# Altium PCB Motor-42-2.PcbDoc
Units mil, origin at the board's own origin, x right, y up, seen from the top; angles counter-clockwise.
Board outline 3535 x 3245 mil, 2 copper layers (Top Layer, Bottom Layer); 0 components, 0 nets, 0 pads, 0 vias.
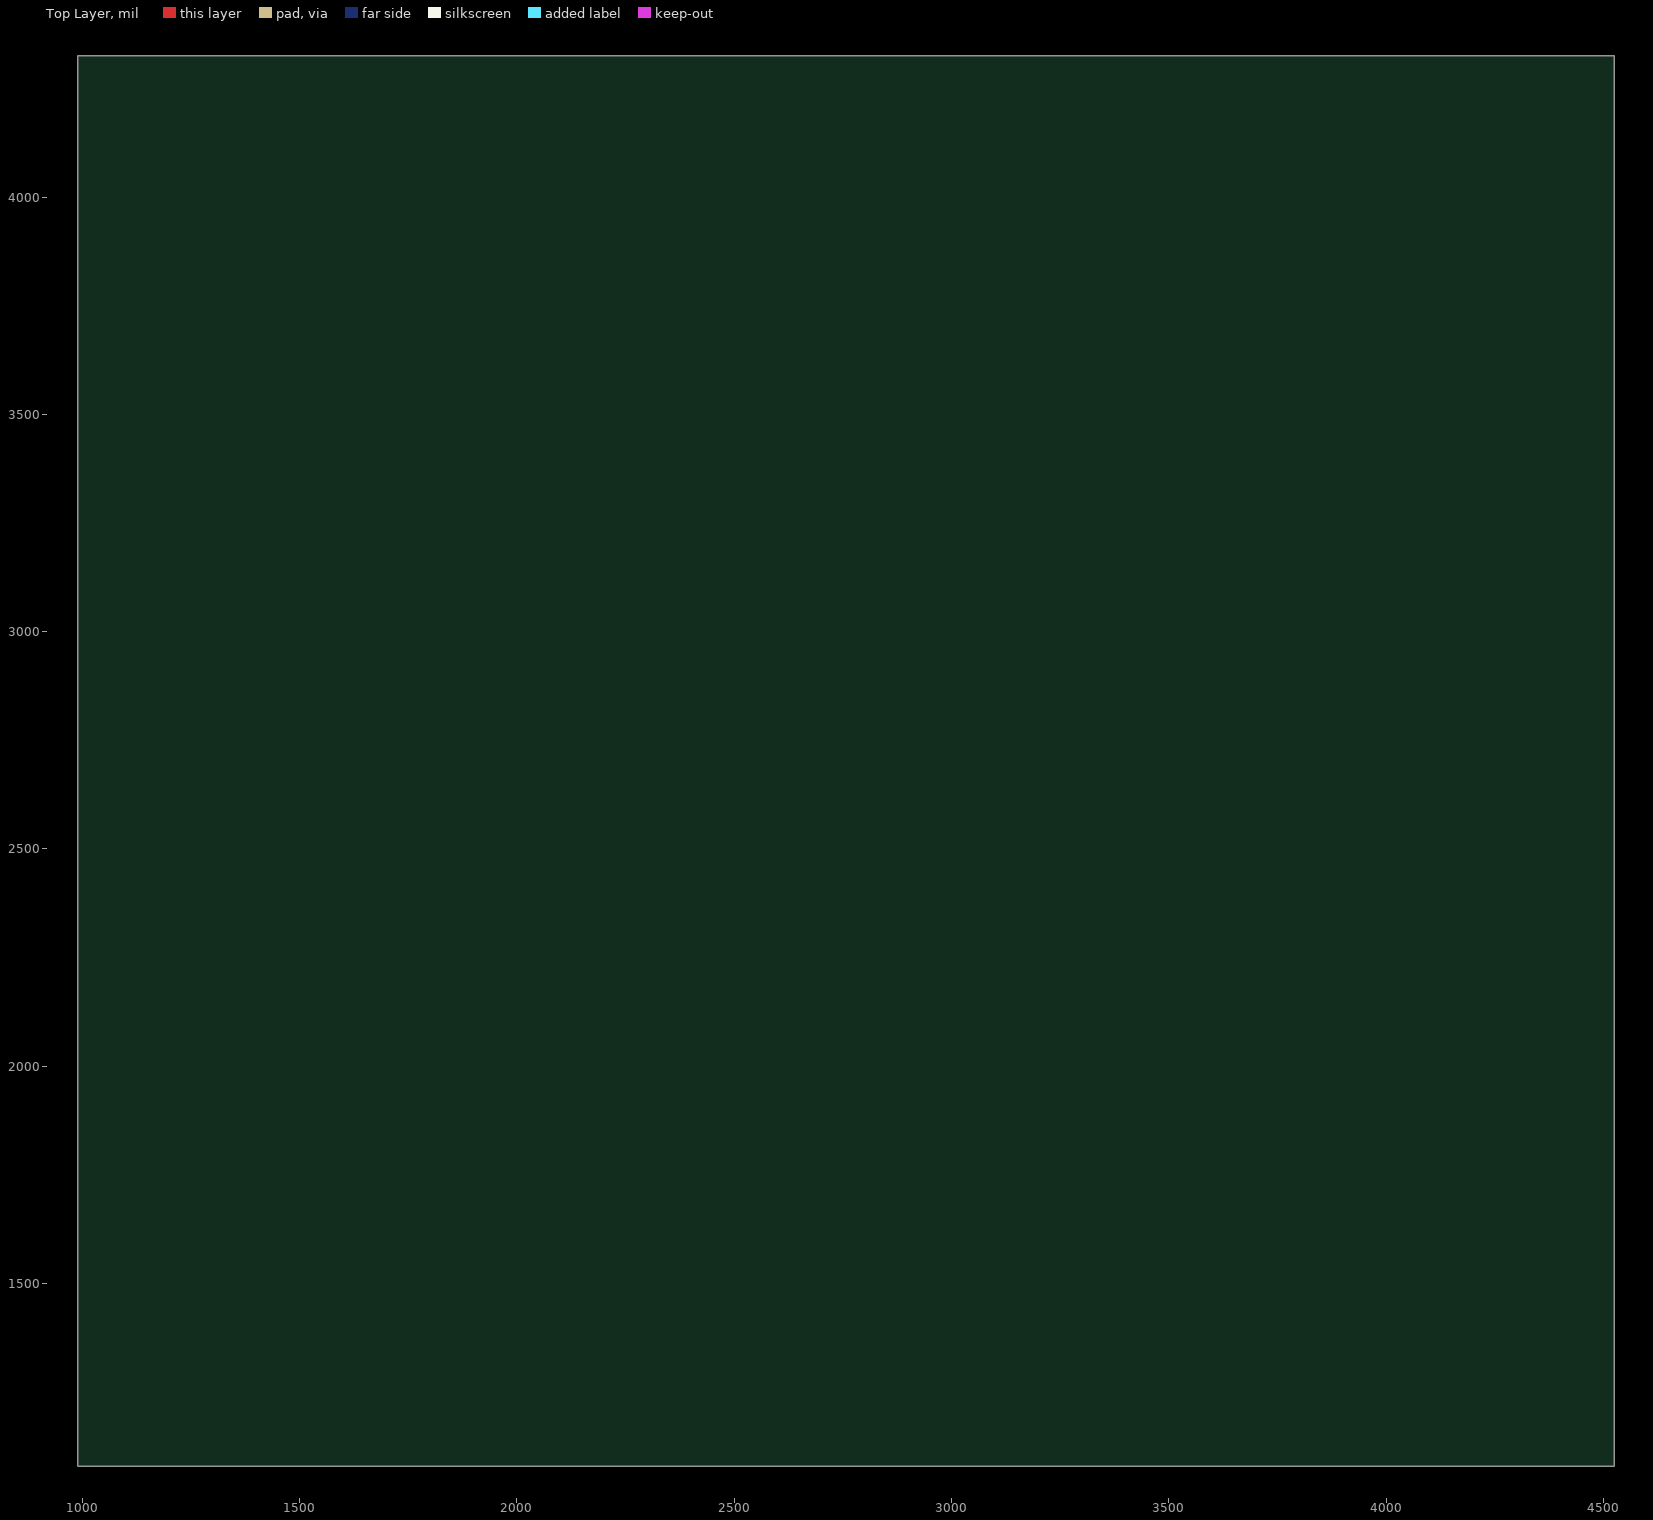
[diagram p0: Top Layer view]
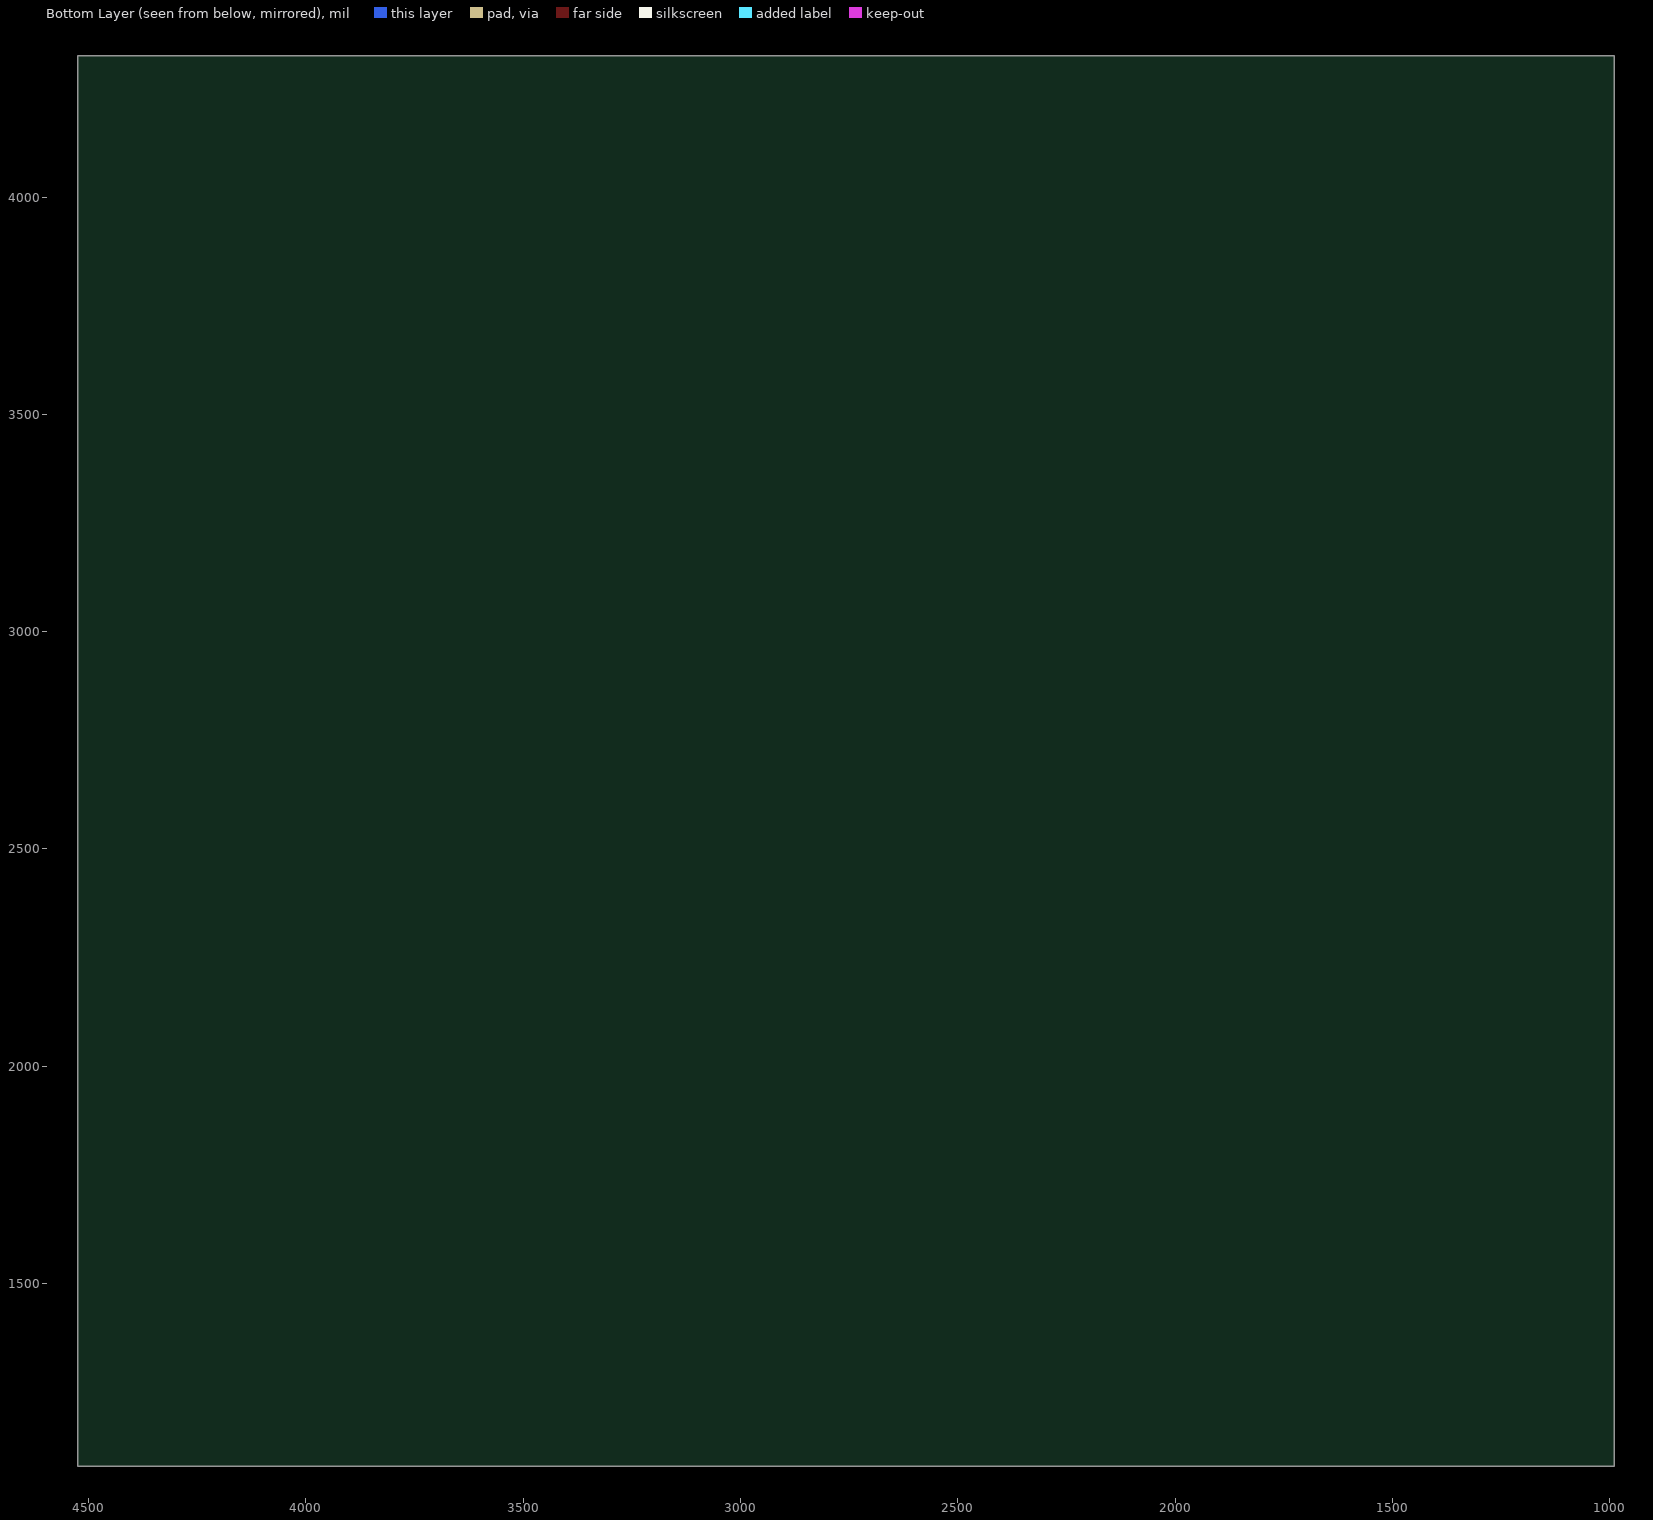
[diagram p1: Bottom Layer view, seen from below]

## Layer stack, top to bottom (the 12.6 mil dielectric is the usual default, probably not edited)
Top Solder: solder mask 0.4, Solder Resist, Dk 3.5
Top Layer: signal copper 1.4
Dielectric 1: dielectric 12.6, FR-4, Dk 4.8
Bottom Layer: signal copper 1.4
Bottom Solder: solder mask 0.4, Solder Resist, Dk 3.5

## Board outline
990,1080 4525,1080 4525,4325 990,4325

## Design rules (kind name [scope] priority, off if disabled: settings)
Clearance [All] p1: gap=10 ignorepadtopadclearanceinfootprint=FALSE except(0: Arc-Hole Track-Hole SMDPad-Hole THPad-Hole Via-Hole Fill-Hole Poly-Hole Region-Hole Text-Hole)
PolygonConnect [All] p1: connectstyle=Relief reliefconductorwidth=10 reliefentries=4 polygonreliefangle="90 Angle" airgapwidth=10
RoutingVias [All] p1: holewidth=28 width=50 viastyle="Through Hole" minholewidth=28 minwidth=50 maxholewidth=28 maxwidth=50
SolderMaskExpansion [All] p1: expansion=4 istentingtop=FALSE
Width [All] p1: maxlimit=10 minlimit=10 preferedwidth=10
30 further rules are at their usual default settings.

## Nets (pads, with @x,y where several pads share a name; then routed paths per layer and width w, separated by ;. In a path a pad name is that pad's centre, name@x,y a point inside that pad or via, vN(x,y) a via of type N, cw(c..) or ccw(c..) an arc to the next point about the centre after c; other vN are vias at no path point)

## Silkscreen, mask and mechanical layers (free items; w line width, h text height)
Mechanical 1:
  the board outline again, w10

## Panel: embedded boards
"Motor-42.PcbDoc" at 1140,1080, 2 rows x 2 columns, spacing 1622.05 x 1622.05, rotation 0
